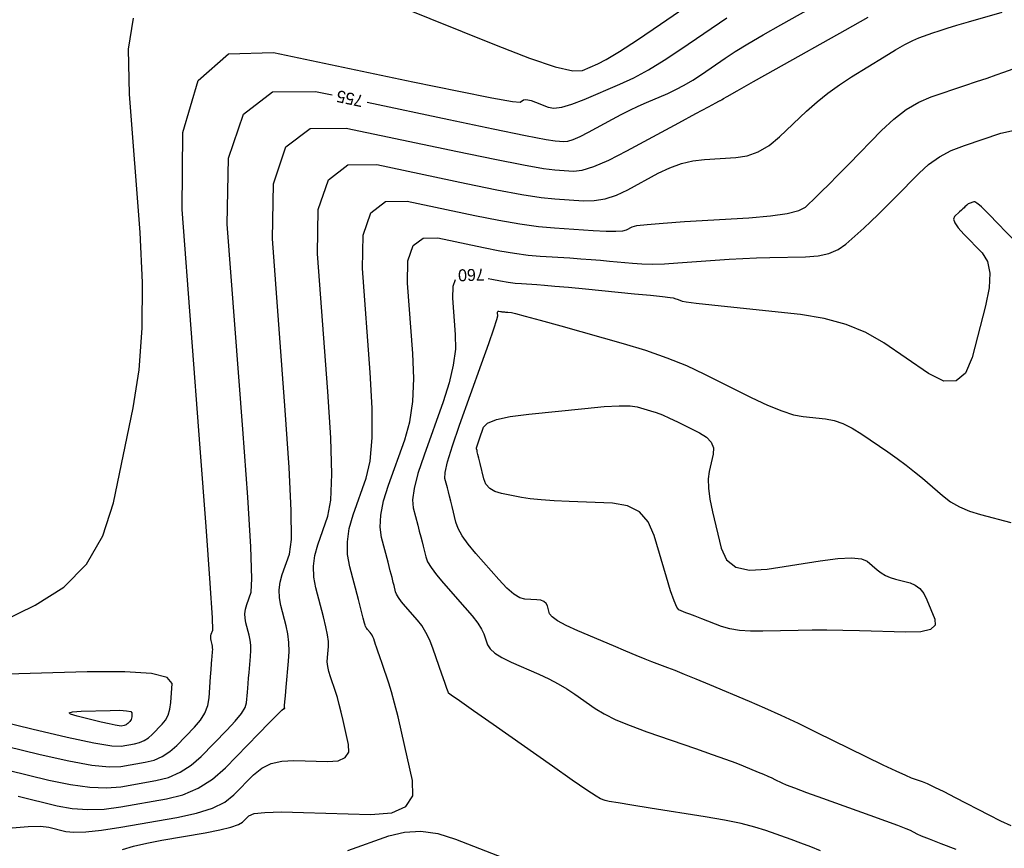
# Model space of a CAD drawing. Extents: x 2082232 to 2083549, y 592624 to 593832.
# Drawn here: x 2082370.6 to 2082428.3, y 592785.8 to 592834.4 of the extents above; entities that cross this region are included whole.
import ezdxf

# ---------------------------------------------------------------- set-up
doc = ezdxf.new("R2010")
doc.units = 0
doc.layers.add('DT_X_Contour_Major', color=7, linetype='Continuous')
doc.layers.add('DT_X_Contour_Minor', color=7, linetype='Continuous')

msp = doc.modelspace()

# ---------------------------------------------------------------- linework, layer by layer
at = {"layer": 'DT_X_Contour_Major'}
for points in [[(2082390.961, 592829.521), (2082395.745, 592828.513), (2082398.33, 592827.971), (2082400.231, 592827.581), (2082401.447, 592827.342), (2082401.978, 592827.255), (2082402.481, 592827.223), (2082402.713, 592827.248), (2082403.029, 592827.348), (2082403.43, 592827.522), (2082403.916, 592827.771), (2082405.325, 592828.533), (2082405.846, 592828.808), (2082406.352, 592829.062), (2082406.843, 592829.295), (2082407.32, 592829.507), (2082408.573, 592830.045), (2082409.048, 592830.265), (2082409.535, 592830.524), (2082410.035, 592830.822), (2082410.546, 592831.158), (2082411.925, 592832.105), (2082412.517, 592832.494), (2082413.259, 592832.95), (2082414.15, 592833.475), (2082415.192, 592834.067), (2082418.168, 592835.736)], [(2082368.72, 592790.656), (2082372.306, 592789.784), (2082373.579, 592789.514), (2082374.707, 592789.36), (2082375.691, 592789.32), (2082376.53, 592789.396), (2082378.576, 592789.751), (2082379.318, 592789.939), (2082380.008, 592790.239), (2082380.648, 592790.649), (2082381.236, 592791.17), (2082382.737, 592792.707), (2082383.232, 592793.24), (2082383.59, 592793.686), (2082383.811, 592794.046), (2082383.896, 592794.319), (2082383.941, 592794.932), (2082383.96, 592795.177), (2082383.983, 592795.452), (2082384.009, 592795.758), (2082384.04, 592796.093), (2082384.126, 592797.029), (2082384.146, 592797.37), (2082384.139, 592797.691), (2082384.107, 592797.993), (2082384.048, 592798.274), (2082383.856, 592798.997), (2082383.805, 592799.268), (2082383.796, 592799.539), (2082383.829, 592799.809), (2082383.904, 592800.079), (2082384.162, 592800.799), (2082384.204, 592801.598), (2082384.136, 592803.457), (2082383.959, 592806.376), (2082383.673, 592810.354), (2082382.765, 592822.376), (2082382.833, 592826.244), (2082383.718, 592828.83), (2082385.419, 592830.135), (2082387.939, 592830.158), (2082388.906, 592829.954)], [(2082429.052, 592821.227), (2082427.854, 592822.468), (2082427.453, 592822.881), (2082427.15, 592823.19), (2082426.945, 592823.393), (2082426.837, 592823.492), (2082426.68, 592823.616), (2082426.621, 592823.654), (2082426.561, 592823.676), (2082426.501, 592823.68), (2082426.441, 592823.668), (2082426.279, 592823.613), (2082426.221, 592823.59), (2082426.169, 592823.562), (2082426.121, 592823.529), (2082426.079, 592823.491), (2082425.973, 592823.383), (2082425.924, 592823.334), (2082425.856, 592823.27), (2082425.769, 592823.189), (2082425.664, 592823.093), (2082425.358, 592822.816), (2082425.307, 592822.674), (2082425.384, 592822.455), (2082425.589, 592822.159), (2082425.922, 592821.786), (2082426.98, 592820.69), (2082427.291, 592820.188), (2082427.428, 592819.504), (2082427.393, 592818.638), (2082427.185, 592817.59), (2082426.398, 592814.553), (2082426.018, 592813.641), (2082425.465, 592813.182), (2082424.74, 592813.175), (2082423.843, 592813.622), (2082421.222, 592815.416), (2082420.18, 592816.024), (2082419.018, 592816.503), (2082417.737, 592816.851), (2082416.336, 592817.07), (2082412.441, 592817.481), (2082411.157, 592817.619), (2082410.227, 592817.724), (2082409.649, 592817.797), (2082409.424, 592817.837), (2082409.295, 592817.902), (2082409.244, 592817.925), (2082409.19, 592817.947), (2082409.131, 592817.968), (2082409.069, 592817.987), (2082408.897, 592818.035), (2082408.706, 592818.064), (2082408.261, 592818.115), (2082407.564, 592818.187), (2082406.614, 592818.281), (2082403.742, 592818.561), (2082402.757, 592818.655), (2082401.956, 592818.728), (2082401.338, 592818.781), (2082400.905, 592818.813), (2082399.995, 592818.87), (2082399.631, 592818.903), (2082399.222, 592818.957), (2082398.769, 592819.034), (2082398.27, 592819.133), (2082398.045, 592819.18)], [(2082396.104, 592819.113), (2082395.973, 592818.729), (2082395.961, 592818.041), (2082396.122, 592815.901), (2082396.123, 592815.053), (2082396.004, 592814.113), (2082395.765, 592813.08), (2082395.406, 592811.955), (2082394.289, 592808.831), (2082393.935, 592807.76), (2082393.711, 592806.886), (2082393.616, 592806.212), (2082393.651, 592805.736), (2082393.918, 592804.732), (2082394.012, 592804.373), (2082394.096, 592804.048), (2082394.17, 592803.757), (2082394.233, 592803.501), (2082394.386, 592802.863), (2082394.495, 592802.587), (2082394.706, 592802.238), (2082395.021, 592801.816), (2082395.438, 592801.321), (2082396.688, 592799.903), (2082397.108, 592799.407), (2082397.432, 592798.985), (2082397.66, 592798.635), (2082397.792, 592798.358), (2082398.015, 592797.715), (2082398.164, 592797.471), (2082398.443, 592797.221), (2082398.853, 592796.964), (2082399.394, 592796.7), (2082401.009, 592795.989), (2082401.595, 592795.716), (2082402.141, 592795.43), (2082402.649, 592795.133), (2082403.117, 592794.823), (2082404.314, 592793.981), (2082404.84, 592793.658), (2082405.52, 592793.323), (2082406.356, 592792.974), (2082407.346, 592792.612), (2082410.192, 592791.63), (2082411.167, 592791.291), (2082411.958, 592791.009), (2082412.564, 592790.785), (2082412.986, 592790.618), (2082413.865, 592790.25), (2082414.172, 592790.12), (2082414.436, 592790.006), (2082414.655, 592789.906), (2082414.831, 592789.823), (2082415.241, 592789.62), (2082415.506, 592789.507), (2082415.992, 592789.32), (2082416.7, 592789.059), (2082417.629, 592788.724), (2082420.401, 592787.731), (2082421.329, 592787.396), (2082422.034, 592787.136), (2082422.515, 592786.949), (2082422.772, 592786.837), (2082423.161, 592786.636), (2082423.414, 592786.523), (2082423.88, 592786.335), (2082424.559, 592786.072), (2082425.451, 592785.734)]]:
    msp.add_lwpolyline(points, dxfattribs=at)
at = {"layer": 'DT_X_Contour_Minor'}
for points in [[(2082392.646, 592835.24), (2082398.506, 592832.869), (2082400.471, 592832.109), (2082401.971, 592831.608), (2082403.007, 592831.365), (2082403.578, 592831.381), (2082404.48, 592831.768), (2082404.963, 592832.023), (2082405.733, 592832.498), (2082406.792, 592833.192), (2082408.138, 592834.106), (2082412.113, 592836.835)], [(2082370.163, 592786.988), (2082371.103, 592787.065), (2082371.816, 592787.076), (2082372.303, 592787.019), (2082373.299, 592786.776), (2082373.78, 592786.724), (2082374.477, 592786.748), (2082375.39, 592786.848), (2082376.519, 592787.024), (2082379.816, 592787.596), (2082380.952, 592787.84), (2082381.888, 592788.14), (2082382.622, 592788.497), (2082383.155, 592788.912), (2082384.308, 592790.093), (2082384.779, 592790.478), (2082385.327, 592790.746), (2082385.952, 592790.898), (2082386.653, 592790.934), (2082388.625, 592790.874), (2082389.258, 592790.92), (2082389.676, 592791.102), (2082389.88, 592791.421), (2082389.869, 592791.876), (2082389.555, 592793.273), (2082389.438, 592793.772), (2082389.323, 592794.221), (2082389.21, 592794.621), (2082389.098, 592794.972), (2082388.802, 592795.84), (2082388.708, 592796.155), (2082388.647, 592796.449), (2082388.62, 592796.721), (2082388.625, 592796.972), (2082388.685, 592797.613), (2082388.683, 592797.903), (2082388.634, 592798.291), (2082388.537, 592798.777), (2082388.393, 592799.362), (2082387.944, 592801.052), (2082387.825, 592801.685), (2082387.804, 592802.318), (2082387.882, 592802.949), (2082388.058, 592803.58), (2082388.659, 592805.261), (2082388.828, 592806.191), (2082388.883, 592807.719), (2082388.825, 592809.847), (2082388.653, 592812.573), (2082388.043, 592820.642), (2082388.089, 592823.238), (2082388.683, 592824.973), (2082389.825, 592825.849), (2082391.516, 592825.865), (2082396.755, 592824.761), (2082398.553, 592824.393), (2082400.017, 592824.12), (2082401.148, 592823.94), (2082401.944, 592823.853), (2082403.623, 592823.748), (2082404.258, 592823.759), (2082404.903, 592823.87), (2082405.559, 592824.082), (2082406.225, 592824.395), (2082408.015, 592825.363), (2082408.688, 592825.686), (2082409.364, 592825.928), (2082410.043, 592826.09), (2082410.725, 592826.172), (2082412.548, 592826.282), (2082413.221, 592826.389), (2082413.873, 592826.626), (2082414.502, 592826.994), (2082415.11, 592827.493), (2082416.702, 592828.998), (2082417.313, 592829.547), (2082417.955, 592830.065), (2082418.627, 592830.553), (2082419.328, 592831.01), (2082421.238, 592832.189), (2082421.903, 592832.59), (2082422.465, 592832.907), (2082422.925, 592833.142), (2082423.283, 592833.294), (2082424.101, 592833.588), (2082424.462, 592833.711), (2082424.931, 592833.86), (2082425.509, 592834.035), (2082426.194, 592834.235), (2082428.168, 592834.804)], [(2082366.546, 592797.615), (2082371.505, 592800.036), (2082373.186, 592801.092), (2082374.511, 592802.445), (2082375.479, 592804.093), (2082376.091, 592806.037), (2082377.247, 592811.617), (2082377.598, 592813.828), (2082377.783, 592816.277), (2082377.801, 592818.964), (2082377.654, 592821.888), (2082377.041, 592830.004), (2082376.983, 592832.637), (2082377.268, 592834.449)], [(2082366.928, 592792.475), (2082371.81, 592791.288), (2082373.479, 592790.909), (2082374.822, 592790.666), (2082375.842, 592790.556), (2082376.536, 592790.582), (2082377.956, 592790.828), (2082378.471, 592790.959), (2082378.95, 592791.167), (2082379.394, 592791.451), (2082379.802, 592791.813), (2082380.844, 592792.879), (2082381.19, 592793.287), (2082381.447, 592793.712), (2082381.614, 592794.152), (2082381.693, 592794.608), (2082381.783, 592795.845), (2082381.814, 592796.266), (2082381.839, 592796.6), (2082381.859, 592796.847), (2082381.872, 592797.006), (2082381.901, 592797.317), (2082381.908, 592797.43), (2082381.905, 592797.537), (2082381.895, 592797.636), (2082381.875, 592797.73), (2082381.811, 592797.97), (2082381.794, 592798.06), (2082381.791, 592798.149), (2082381.803, 592798.239), (2082381.828, 592798.329), (2082381.913, 592798.567), (2082381.891, 592799.302), (2082381.763, 592801.326), (2082381.527, 592804.641), (2082381.183, 592809.245), (2082380.126, 592823.243), (2082380.162, 592827.756), (2082381.063, 592830.794), (2082382.829, 592832.359), (2082385.461, 592832.45), (2082393.633, 592830.727), (2082396.324, 592830.168), (2082398.268, 592829.782), (2082399.465, 592829.57), (2082399.915, 592829.531), (2082400.118, 592829.658), (2082400.219, 592829.686), (2082400.369, 592829.674), (2082400.57, 592829.622), (2082400.821, 592829.53), (2082401.555, 592829.233), (2082401.894, 592829.177), (2082402.361, 592829.234), (2082402.954, 592829.402), (2082403.675, 592829.683), (2082405.766, 592830.58), (2082406.578, 592830.961), (2082407.444, 592831.43), (2082408.366, 592831.987), (2082409.342, 592832.632), (2082412.019, 592834.47)], [(2082370.511, 592788.838), (2082372.803, 592788.28), (2082373.68, 592788.119), (2082374.592, 592788.054), (2082375.541, 592788.084), (2082376.525, 592788.21), (2082379.196, 592788.674), (2082380.164, 592788.919), (2082381.062, 592789.306), (2082381.892, 592789.836), (2082382.652, 592790.508), (2082384.588, 592792.491), (2082385.225, 592793.141), (2082385.684, 592793.606), (2082385.965, 592793.885), (2082386.069, 592793.977), (2082386.106, 592793.976), (2082386.118, 592793.977), (2082386.126, 592793.98), (2082386.13, 592793.986), (2082386.13, 592793.995), (2082386.124, 592794.022), (2082386.122, 592794.031), (2082386.119, 592794.04), (2082386.117, 592794.047), (2082386.115, 592794.054), (2082386.109, 592794.07), (2082386.114, 592794.148), (2082386.133, 592794.367), (2082386.165, 592794.728), (2082386.212, 592795.232), (2082386.354, 592796.764), (2082386.385, 592797.323), (2082386.374, 592797.852), (2082386.319, 592798.35), (2082386.22, 592798.818), (2082385.9, 592800.024), (2082385.815, 592800.477), (2082385.8, 592800.928), (2082385.856, 592801.379), (2082385.981, 592801.83), (2082386.411, 592803.03), (2082386.516, 592803.894), (2082386.51, 592805.588), (2082386.392, 592808.111), (2082386.163, 592811.464), (2082385.404, 592821.509), (2082385.461, 592824.741), (2082386.2, 592826.902), (2082387.622, 592827.992), (2082389.727, 592828.012), (2082396.25, 592826.637), (2082398.442, 592826.182), (2082400.124, 592825.85), (2082401.297, 592825.641), (2082401.961, 592825.554), (2082403.052, 592825.485), (2082403.553, 592825.54), (2082404.239, 592825.757), (2082405.108, 592826.134), (2082406.161, 592826.673), (2082409.214, 592828.324), (2082410.22, 592828.868), (2082410.946, 592829.259), (2082411.392, 592829.499), (2082411.56, 592829.586), (2082411.633, 592829.618), (2082411.661, 592829.631), (2082411.69, 592829.646), (2082411.72, 592829.664), (2082411.75, 592829.684), (2082411.831, 592829.74), (2082412.047, 592829.864), (2082412.633, 592830.195), (2082413.591, 592830.734), (2082414.919, 592831.479), (2082418.955, 592833.743), (2082420.316, 592834.515)], [(2082376.623, 592785.707), (2082377.273, 592785.903), (2082378.043, 592786.087), (2082378.935, 592786.259), (2082381.474, 592786.699), (2082382.325, 592786.862), (2082382.972, 592787.018), (2082383.417, 592787.169), (2082383.657, 592787.315), (2082384.028, 592787.695), (2082384.333, 592787.814), (2082384.97, 592787.886), (2082385.938, 592787.912), (2082387.237, 592787.891), (2082391.145, 592787.772), (2082392.398, 592787.863), (2082393.226, 592788.224), (2082393.63, 592788.856), (2082393.609, 592789.758), (2082392.987, 592792.524), (2082392.764, 592793.486), (2082392.563, 592794.297), (2082392.383, 592794.957), (2082392.225, 592795.467), (2082391.831, 592796.623), (2082391.697, 592797.018), (2082391.589, 592797.335), (2082391.507, 592797.573), (2082391.452, 592797.734), (2082391.339, 592798.057), (2082391.295, 592798.172), (2082391.247, 592798.272), (2082391.195, 592798.359), (2082391.14, 592798.431), (2082390.986, 592798.606), (2082390.935, 592798.666), (2082390.896, 592798.718), (2082390.87, 592798.761), (2082390.857, 592798.795), (2082390.838, 592798.874), (2082390.808, 592798.989), (2082390.732, 592799.276), (2082390.61, 592799.735), (2082390.443, 592800.366), (2082389.936, 592802.276), (2082389.806, 592803.005), (2082389.796, 592803.756), (2082389.905, 592804.532), (2082390.135, 592805.33), (2082390.908, 592807.492), (2082391.14, 592808.487), (2082391.257, 592809.85), (2082391.257, 592811.582), (2082391.143, 592813.683), (2082390.682, 592819.775), (2082390.717, 592821.735), (2082391.165, 592823.045), (2082392.028, 592823.707), (2082393.304, 592823.719), (2082397.26, 592822.885), (2082398.665, 592822.604), (2082399.911, 592822.389), (2082400.998, 592822.238), (2082401.927, 592822.152), (2082404.194, 592822.01), (2082404.953, 592821.972), (2082405.531, 592821.964), (2082405.928, 592821.986), (2082406.143, 592822.038), (2082406.475, 592822.218), (2082406.761, 592822.288), (2082407.369, 592822.362), (2082408.299, 592822.441), (2082409.551, 592822.524), (2082413.32, 592822.752), (2082414.587, 592822.855), (2082415.561, 592822.994), (2082416.242, 592823.17), (2082416.631, 592823.381), (2082417.277, 592823.992), (2082417.579, 592824.283), (2082417.998, 592824.701), (2082418.536, 592825.245), (2082419.192, 592825.915), (2082421.099, 592827.868), (2082421.816, 592828.54), (2082422.539, 592829.091), (2082423.268, 592829.522), (2082424.002, 592829.832), (2082425.967, 592830.497), (2082426.663, 592830.734), (2082427.276, 592830.945), (2082427.808, 592831.131), (2082428.258, 592831.291), (2082429.347, 592831.682)], [(2082417.519, 592785.642), (2082416.94, 592785.873), (2082416.368, 592786.091), (2082415.804, 592786.298), (2082414.311, 592786.832), (2082413.669, 592787.031), (2082412.864, 592787.229), (2082411.897, 592787.424), (2082410.766, 592787.618), (2082407.533, 592788.133), (2082406.459, 592788.306), (2082405.662, 592788.44), (2082405.143, 592788.535), (2082404.901, 592788.591), (2082404.625, 592788.686), (2082404.371, 592788.832), (2082403.817, 592789.199), (2082402.963, 592789.786), (2082401.81, 592790.594), (2082398.332, 592793.042), (2082397.191, 592793.845), (2082396.376, 592794.419), (2082395.887, 592794.764), (2082395.723, 592794.879), (2082395.722, 592794.88), (2082395.697, 592794.949), (2082395.625, 592795.157), (2082395.504, 592795.503), (2082395.336, 592795.987), (2082394.824, 592797.463), (2082394.623, 592797.985), (2082394.404, 592798.442), (2082394.168, 592798.837), (2082393.914, 592799.167), (2082393.212, 592799.963), (2082392.978, 592800.241), (2082392.801, 592800.478), (2082392.682, 592800.674), (2082392.621, 592800.829), (2082392.535, 592801.187), (2082392.489, 592801.373), (2082392.414, 592801.662), (2082392.311, 592802.054), (2082392.18, 592802.549), (2082391.794, 592804.006), (2082391.711, 592804.608), (2082391.753, 592805.321), (2082391.92, 592806.146), (2082392.212, 592807.081), (2082393.157, 592809.723), (2082393.452, 592810.783), (2082393.63, 592811.981), (2082393.69, 592813.318), (2082393.632, 592814.792), (2082393.321, 592818.908), (2082393.345, 592820.232), (2082393.648, 592821.117), (2082394.23, 592821.564), (2082395.093, 592821.572), (2082397.765, 592821.009), (2082398.724, 592820.819), (2082399.597, 592820.671), (2082400.383, 592820.566), (2082401.083, 592820.504), (2082402.835, 592820.394), (2082403.472, 592820.352), (2082404.072, 592820.307), (2082404.634, 592820.261), (2082405.158, 592820.213), (2082406.504, 592820.082), (2082407.048, 592820.047), (2082407.672, 592820.039), (2082408.374, 592820.059), (2082409.156, 592820.106), (2082411.346, 592820.269), (2082412.162, 592820.325), (2082412.969, 592820.368), (2082413.766, 592820.399), (2082414.553, 592820.419), (2082416.641, 592820.454), (2082417.375, 592820.51), (2082418.012, 592820.652), (2082418.552, 592820.881), (2082418.995, 592821.195), (2082420.048, 592822.146), (2082420.459, 592822.526), (2082420.903, 592822.951), (2082421.379, 592823.422), (2082421.889, 592823.938), (2082423.291, 592825.375), (2082423.852, 592825.88), (2082424.482, 592826.319), (2082425.18, 592826.691), (2082425.948, 592826.996), (2082428.088, 592827.721), (2082428.888, 592827.882)], [(2082428.687, 592787.09), (2082428.09, 592787.38), (2082427.399, 592787.73), (2082425.432, 592788.744), (2082424.757, 592789.088), (2082424.207, 592789.357), (2082423.783, 592789.553), (2082423.483, 592789.675), (2082422.85, 592789.901), (2082422.506, 592790.043), (2082421.95, 592790.297), (2082421.18, 592790.665), (2082420.197, 592791.146), (2082417.291, 592792.58), (2082416.228, 592793.096), (2082415.219, 592793.569), (2082414.264, 592794), (2082413.363, 592794.387), (2082411.032, 592795.363), (2082410.223, 592795.699), (2082409.545, 592795.978), (2082408.997, 592796.199), (2082408.58, 592796.361), (2082407.641, 592796.717), (2082407.236, 592796.875), (2082406.724, 592797.083), (2082406.106, 592797.34), (2082405.381, 592797.648), (2082403.305, 592798.533), (2082402.618, 592798.845), (2082402.112, 592799.116), (2082401.789, 592799.347), (2082401.649, 592799.538), (2082401.516, 592799.993), (2082401.44, 592800.143), (2082401.311, 592800.254), (2082401.129, 592800.324), (2082400.894, 592800.354), (2082400.196, 592800.38), (2082399.904, 592800.46), (2082399.552, 592800.68), (2082399.139, 592801.041), (2082398.666, 592801.542), (2082397.323, 592803.065), (2082396.872, 592803.608), (2082396.526, 592804.094), (2082396.286, 592804.524), (2082396.15, 592804.896), (2082395.93, 592805.814), (2082395.851, 592806.141), (2082395.779, 592806.434), (2082395.714, 592806.692), (2082395.655, 592806.916), (2082395.509, 592807.466), (2082395.522, 592807.816), (2082395.669, 592808.451), (2082395.95, 592809.374), (2082396.366, 592810.582), (2082397.655, 592814.186), (2082398.077, 592815.376), (2082398.377, 592816.244), (2082398.556, 592816.789), (2082398.612, 592817.011), (2082398.6, 592817.174)], [(2082398.6, 592817.174), (2082398.601, 592817.226), (2082398.613, 592817.261), (2082398.636, 592817.278), (2082398.67, 592817.279), (2082398.775, 592817.257), (2082398.813, 592817.249), (2082398.848, 592817.243), (2082398.879, 592817.239), (2082398.906, 592817.237), (2082398.976, 592817.232), (2082399.009, 592817.23), (2082399.056, 592817.226), (2082399.116, 592817.22), (2082399.191, 592817.213), (2082399.41, 592817.192), (2082399.652, 592817.137), (2082400.215, 592816.988), (2082401.1, 592816.744), (2082402.305, 592816.407), (2082405.946, 592815.381), (2082407.269, 592814.981), (2082408.507, 592814.548), (2082409.66, 592814.084), (2082410.728, 592813.588), (2082413.461, 592812.223), (2082414.419, 592811.768), (2082415.245, 592811.429), (2082415.937, 592811.204), (2082416.496, 592811.095), (2082417.809, 592810.956), (2082418.312, 592810.862), (2082418.833, 592810.683), (2082419.375, 592810.419), (2082419.936, 592810.07), (2082421.459, 592809.028), (2082422.014, 592808.638), (2082422.537, 592808.25), (2082423.027, 592807.864), (2082423.485, 592807.48), (2082424.665, 592806.46), (2082425.135, 592806.103), (2082425.662, 592805.799), (2082426.246, 592805.547), (2082426.886, 592805.347), (2082428.668, 592804.885)], [(2082397.367, 592809.196), (2082397.37, 592809.26), (2082397.399, 592809.38), (2082397.453, 592809.555), (2082397.532, 592809.786), (2082397.779, 592810.475), (2082398.014, 592810.717), (2082398.534, 592810.926), (2082399.34, 592811.101), (2082400.43, 592811.243), (2082403.719, 592811.578), (2082404.835, 592811.677), (2082405.717, 592811.724), (2082406.364, 592811.719), (2082406.777, 592811.662), (2082407.566, 592811.44), (2082407.885, 592811.337), (2082408.253, 592811.194), (2082408.667, 592811.011), (2082409.13, 592810.788), (2082410.426, 592810.14), (2082410.841, 592809.88), (2082411.112, 592809.585), (2082411.239, 592809.256), (2082411.223, 592808.893), (2082410.988, 592807.877), (2082410.934, 592807.443), (2082410.95, 592806.905), (2082411.035, 592806.262), (2082411.188, 592805.515), (2082411.69, 592803.381), (2082412, 592802.704), (2082412.554, 592802.272), (2082413.35, 592802.086), (2082414.39, 592802.146), (2082417.488, 592802.632), (2082418.532, 592802.768), (2082419.34, 592802.811), (2082419.913, 592802.761), (2082420.25, 592802.618), (2082420.834, 592802.112), (2082421.066, 592801.935), (2082421.323, 592801.785), (2082421.605, 592801.662), (2082421.913, 592801.566), (2082422.766, 592801.344), (2082423.067, 592801.219), (2082423.332, 592801.01), (2082423.56, 592800.718), (2082423.752, 592800.341), (2082424.213, 592799.224), (2082424.237, 592798.861), (2082423.963, 592798.611), (2082423.391, 592798.473), (2082422.521, 592798.448), (2082419.804, 592798.532), (2082418.815, 592798.557), (2082417.887, 592798.569), (2082417.02, 592798.568), (2082416.213, 592798.555), (2082414.143, 592798.504), (2082413.409, 592798.507), (2082412.761, 592798.557), (2082412.198, 592798.653), (2082411.721, 592798.794), (2082410.563, 592799.234), (2082410.17, 592799.383), (2082409.861, 592799.502), (2082409.635, 592799.591), (2082409.493, 592799.649), (2082409.224, 592799.763), (2082409.103, 592799.915), (2082408.94, 592800.285), (2082408.736, 592800.872), (2082408.49, 592801.678), (2082407.78, 592804.116), (2082407.428, 592804.92), (2082406.904, 592805.505), (2082406.207, 592805.87), (2082405.339, 592806.016), (2082402.794, 592806.111), (2082401.904, 592806.153), (2082401.143, 592806.208), (2082400.51, 592806.276), (2082400.006, 592806.356), (2082398.835, 592806.587), (2082398.44, 592806.706), (2082398.135, 592806.887), (2082397.919, 592807.132), (2082397.793, 592807.44), (2082397.575, 592808.346), (2082397.502, 592808.648), (2082397.448, 592808.874), (2082397.411, 592809.024), (2082397.393, 592809.099), (2082397.367, 592809.196)], [(2082365.136, 592794.294), (2082371.314, 592792.791), (2082373.378, 592792.305), (2082374.937, 592791.972), (2082375.992, 592791.793), (2082376.542, 592791.767), (2082377.336, 592791.905), (2082377.624, 592791.978), (2082377.892, 592792.094), (2082378.14, 592792.254), (2082378.368, 592792.456), (2082378.951, 592793.052), (2082379.145, 592793.3), (2082379.293, 592793.595), (2082379.394, 592793.939), (2082379.448, 592794.33), (2082379.529, 592795.438), (2082379.241, 592795.793), (2082378.317, 592796.026), (2082376.757, 592796.138), (2082374.561, 592796.128), (2082367.855, 592795.94)], [(2082373.966, 592793.529), (2082373.586, 592793.643), (2082373.498, 592793.73), (2082373.702, 592793.789), (2082374.197, 592793.821), (2082375.909, 592793.869), (2082376.47, 592793.874), (2082376.868, 592793.852), (2082377.105, 592793.804), (2082377.179, 592793.729), (2082377.162, 592793.495), (2082377.151, 592793.412), (2082377.13, 592793.34), (2082377.098, 592793.277), (2082377.057, 592793.225), (2082376.934, 592793.099), (2082376.886, 592793.056), (2082376.833, 592793.022), (2082376.777, 592792.998), (2082376.716, 592792.982), (2082376.548, 592792.953), (2082376.427, 592792.96), (2082376.191, 592793.001), (2082375.838, 592793.077), (2082375.37, 592793.187), (2082373.966, 592793.529)], [(2082389.826, 592785.651), (2082392.231, 592786.507), (2082393.152, 592786.736), (2082394.11, 592786.782), (2082395.106, 592786.645), (2082396.14, 592786.325), (2082398.946, 592785.226)]]:
    msp.add_lwpolyline(points, dxfattribs=at)

# ---------------------------------------------------------------- texts
at = {"layer": 'DT_X_Contour_Major'}
for s, rotation, p in [('755', 168.09671, (2082390.779, 592829.917)), ('760', 181.98369, (2082397.832, 592819.775))]:
    msp.add_text(s, height=0.7, rotation=rotation, dxfattribs=at).set_placement(p)

doc.saveas('drawing.dxf')
